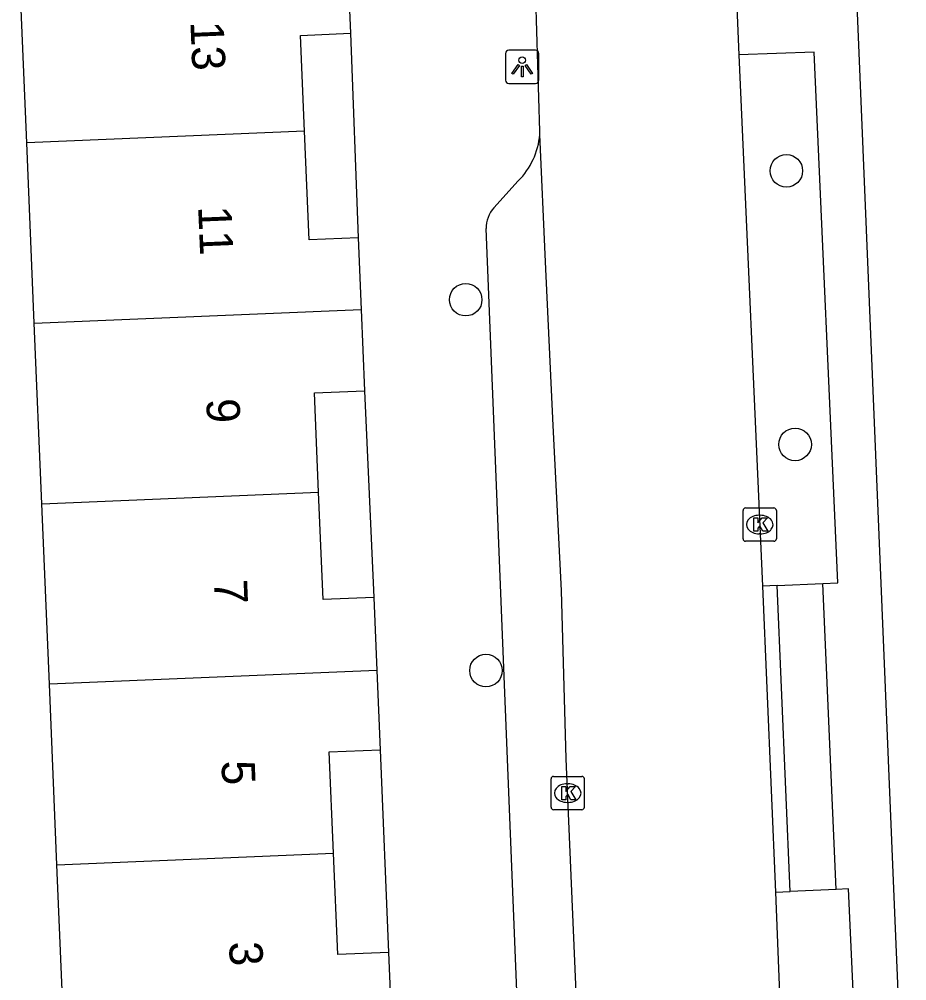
# Model space of a CAD drawing. Extents: x 161243 to 161752, y 384138 to 384885.
# Drawn here: x 161357.85 to 161384.53, y 384214.34 to 384243.24 of the extents above; entities that cross this region are included whole.
import ezdxf

# ---------------------------------------------------------------- set-up
doc = ezdxf.new("R2010")
doc.units = 0
for name, color, linetype in [('IMGEO_Boom', 7, 'Continuous'), ('IMGEO_Kolk', 7, 'Continuous'), ('IMGEO_Lichtpunt', 7, 'Continuous'), ('IMGEO_Pand', 7, 'Continuous'), ('IMGEO_Pand_nummerreeks', 7, 'Continuous'), ('IMGEO_Rijbaan_lokaal_open', 7, 'Continuous'), ('IMGEO_Voetpad_gesloten', 7, 'Continuous'), ('IMGEO_Voetpad_open', 7, 'Continuous')]:
    doc.layers.add(name, color=color, linetype=linetype)

msp = doc.modelspace()

# ---------------------------------------------------------------- linework, layer by layer
at = {"layer": 'IMGEO_Boom'}
for centre in [(161380.908, 384238.68), (161371.269, 384234.808), (161381.169, 384230.459), (161371.877, 384223.663)]:
    msp.add_circle(centre, 0.489, dxfattribs=at)
at = {"layer": 'IMGEO_Kolk'}
for p, q in [((161379.606, 384227.623), (161379.606, 384228.475)), ((161379.681, 384228.549), (161380.533, 384228.549)), ((161380.607, 384228.475), (161380.607, 384227.623)), ((161380.094, 384228.329), (161380.119, 384228.329)), ((161380.533, 384227.549), (161379.681, 384227.549)), ((161380.117, 384227.769), (161380.092, 384227.769)), ((161373.833, 384219.556), (161373.833, 384220.408)), ((161373.908, 384220.482), (161374.76, 384220.482)), ((161374.834, 384220.408), (161374.834, 384219.556)), ((161374.321, 384220.262), (161374.346, 384220.262)), ((161374.344, 384219.702), (161374.319, 384219.702)), ((161374.76, 384219.482), (161373.908, 384219.482))]:
    msp.add_line(p, q, dxfattribs=at)
for points in [[(161379.606, 384227.623), (161379.606, 384228.475)], [(161379.681, 384228.549), (161380.533, 384228.549)], [(161380.607, 384228.475), (161380.607, 384227.623)], [(161379.927, 384228.249), (161380.05, 384228.249), (161380.05, 384228.098), (161380.18, 384228.249), (161380.344, 384228.249), (161380.198, 384228.098), (161380.351, 384227.849), (161380.199, 384227.849), (161380.114, 384228.013), (161380.05, 384227.946), (161380.05, 384227.849), (161379.927, 384227.849), (161379.927, 384228.249)], [(161380.533, 384227.549), (161379.681, 384227.549)], [(161373.833, 384219.556), (161373.833, 384220.408)], [(161373.908, 384220.482), (161374.76, 384220.482)], [(161374.834, 384220.408), (161374.834, 384219.556)], [(161374.154, 384220.182), (161374.277, 384220.182), (161374.277, 384220.031), (161374.407, 384220.182), (161374.571, 384220.182), (161374.425, 384220.031), (161374.578, 384219.782), (161374.426, 384219.782), (161374.341, 384219.946), (161374.277, 384219.879), (161374.277, 384219.782), (161374.154, 384219.782), (161374.154, 384220.182)], [(161374.76, 384219.482), (161373.908, 384219.482)]]:
    msp.add_lwpolyline(points, dxfattribs=at)
for centre, start, end in [((161379.683, 384228.473), 91.552, 178.448), ((161379.683, 384228.473), 91.552, 178.448), ((161380.531, 384228.473), 1.552, 88.448), ((161380.531, 384228.473), 1.552, 88.448), ((161379.683, 384227.625), 181.552, 268.448), ((161379.683, 384227.625), 181.552, 268.448), ((161380.531, 384227.625), 271.552, 358.448), ((161380.531, 384227.625), 271.552, 358.448), ((161373.91, 384220.406), 91.552, 178.448), ((161373.91, 384220.406), 91.552, 178.448), ((161374.758, 384220.406), 1.552, 88.448), ((161374.758, 384220.406), 1.552, 88.448), ((161373.91, 384219.558), 181.552, 268.448), ((161373.91, 384219.558), 181.552, 268.448), ((161374.758, 384219.558), 271.552, 358.448), ((161374.758, 384219.558), 271.552, 358.448)]:
    msp.add_arc(centre, 0.0765, start, end, dxfattribs=at)
for centre, major_axis, ratio, start_param, end_param in [((161380.093, 384228.049), (-0.387, 0.002), 0.722429, 4.712389, 7.853982), ((161380.118, 384228.049), (-0.39, 0.002), 0.717154, 1.570796, 4.712389), ((161374.32, 384219.982), (-0.387, 0.002), 0.722429, 4.712389, 7.853982), ((161374.345, 384219.982), (-0.39, 0.002), 0.717154, 1.570796, 4.712389)]:
    msp.add_ellipse(centre, major_axis=major_axis, ratio=ratio, start_param=start_param, end_param=end_param, dxfattribs=at)
at = {"layer": 'IMGEO_Lichtpunt'}
for p, q in [((161373.37, 384242.303), (161372.562, 384242.303)), ((161373.37, 384242.303), (161372.562, 384242.303)), ((161372.468, 384242.208), (161372.468, 384241.401)), ((161372.468, 384242.208), (161372.468, 384241.401)), ((161373.464, 384241.401), (161373.464, 384242.208)), ((161373.464, 384241.401), (161373.464, 384242.208)), ((161372.562, 384241.307), (161373.37, 384241.307)), ((161372.562, 384241.307), (161373.37, 384241.307))]:
    msp.add_line(p, q, dxfattribs=at)
for points in [[(161372.842, 384241.872), (161372.881, 384241.844), (161372.693, 384241.582), (161372.655, 384241.609), (161372.842, 384241.872)], [(161372.944, 384241.824), (161372.991, 384241.824), (161372.991, 384241.502), (161372.944, 384241.502), (161372.944, 384241.824)], [(161373.054, 384241.844), (161373.092, 384241.871), (161373.279, 384241.609), (161373.24, 384241.581), (161373.054, 384241.844)]]:
    msp.add_lwpolyline(points, dxfattribs=at)
msp.add_circle((161372.967, 384242.006), 0.0994, dxfattribs=at)
for centre, start, end in [((161372.562, 384242.208), 90, 180), ((161372.562, 384242.208), 90, 180), ((161373.37, 384242.208), 0, 90), ((161373.37, 384242.208), 0, 90), ((161372.562, 384241.401), 180, 270), ((161372.562, 384241.401), 180, 270), ((161373.37, 384241.401), 270, 0), ((161373.37, 384241.401), 270, 360)]:
    msp.add_arc(centre, 0.0946, start, end, dxfattribs=at)
at = {"layer": 'IMGEO_Pand'}
for points in [[(161367.698, 384245.357), (161367.806, 384242.815)], [(161358.075, 384239.523), (161357.848, 384244.946)], [(161366.423, 384239.871), (161366.301, 384242.751), (161367.806, 384242.815)], [(161366.423, 384239.871), (161358.075, 384239.523)], [(161368.033, 384236.668), (161366.562, 384236.605), (161366.423, 384239.871)], [(161358.302, 384234.099), (161358.075, 384239.523)], [(161368.033, 384236.668), (161368.125, 384234.509)], [(161358.302, 384234.099), (161368.125, 384234.509)], [(161368.125, 384234.509), (161368.228, 384232.07)], [(161358.529, 384228.676), (161358.302, 384234.099)], [(161366.848, 384229.023), (161366.722, 384232.006), (161368.228, 384232.07)], [(161358.529, 384228.676), (161366.848, 384229.023)], [(161368.506, 384225.862), (161366.985, 384225.797), (161366.848, 384229.023)], [(161358.756, 384223.252), (161358.529, 384228.676)], [(161368.506, 384225.862), (161368.6, 384223.663)], [(161368.6, 384223.663), (161358.756, 384223.252)], [(161368.6, 384223.663), (161368.701, 384221.283)], [(161358.982, 384217.829), (161358.756, 384223.252)], [(161367.296, 384218.175), (161367.167, 384221.218), (161368.701, 384221.283)], [(161358.982, 384217.829), (161367.296, 384218.175)], [(161368.949, 384215.194), (161367.426, 384215.13), (161367.296, 384218.175)], [(161359.209, 384212.406), (161358.982, 384217.829)], [(161368.949, 384215.194), (161369.05, 384212.817)]]:
    msp.add_lwpolyline(points, dxfattribs=at)
at = {"layer": 'IMGEO_Rijbaan_lokaal_open'}
for points in [[(161373.499, 384239.768), (161373.501, 384239.874), (161373.376, 384243.89), (161373.336, 384246.428), (161373.313, 384246.58), (161373.282, 384246.79)], [(161379.324, 384245.758), (161379.483, 384242.162)], [(161379.483, 384242.162), (161380.186, 384226.202)], [(161374.869, 384207.368), (161374.743, 384210.484), (161374.291, 384221.013), (161374.148, 384226.066), (161373.902, 384231.03), (161373.666, 384235.944), (161373.499, 384239.768)], [(161380.186, 384226.202), (161380.576, 384217.009)], [(161380.576, 384217.009), (161380.876, 384209.619), (161380.967, 384207.431)]]:
    msp.add_lwpolyline(points, dxfattribs=at)
at = {"layer": 'IMGEO_Voetpad_gesloten'}
for points in [[(161380.635, 384226.221), (161380.186, 384226.202)], [(161380.635, 384226.221), (161382.002, 384226.279)], [(161381.026, 384217.028), (161380.635, 384226.221)], [(161382.4, 384217.089), (161382.002, 384226.279)], [(161380.576, 384217.009), (161381.026, 384217.028)], [(161382.4, 384217.089), (161381.026, 384217.028)]]:
    msp.add_lwpolyline(points, dxfattribs=at)
at = {"layer": 'IMGEO_Voetpad_open'}
for points in [[(161385.58, 384183.057), (161384.168, 384216.383), (161381.889, 384271.203), (161381.629, 384276.193), (161382.268, 384292.057), (161382.629, 384295.041)], [(161367.806, 384242.815), (161368.033, 384236.668)], [(161382.002, 384226.279), (161382.455, 384226.302), (161381.747, 384242.244), (161379.483, 384242.162)], [(161372.115, 384237.573), (161372.849, 384238.377)], [(161372.97, 384210.041), (161371.886, 384236.944)], [(161368.228, 384232.07), (161368.506, 384225.862)], [(161368.701, 384221.283), (161368.949, 384215.194)], [(161381.36, 384197.944), (161383.651, 384198.05), (161382.773, 384217.109), (161382.4, 384217.089)]]:
    msp.add_lwpolyline(points, dxfattribs=at)
for centre, radius, start, end in [((161371.235, 384239.978), 2.273, 315.2178, 354.6898), ((161372.762, 384236.981), 0.876, 137.5439, 182.446)]:
    msp.add_arc(centre, radius, start, end, dxfattribs=at)

# ---------------------------------------------------------------- texts
at = {"layer": 'IMGEO_Pand_nummerreeks'}
for s, p in [('13', (161362.992, 384243.159)), ('11', (161363.225, 384237.607)), ('9', (161363.468, 384231.823)), ('7', (161363.697, 384226.384)), ('5', (161363.925, 384220.946)), ('3', (161364.154, 384215.508))]:
    msp.add_text(s, height=1, rotation=272.4061, dxfattribs=at).set_placement(p)

doc.saveas('drawing.dxf')
